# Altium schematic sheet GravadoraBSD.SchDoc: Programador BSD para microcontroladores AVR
size A4; Author: Geovany Araujo Borges
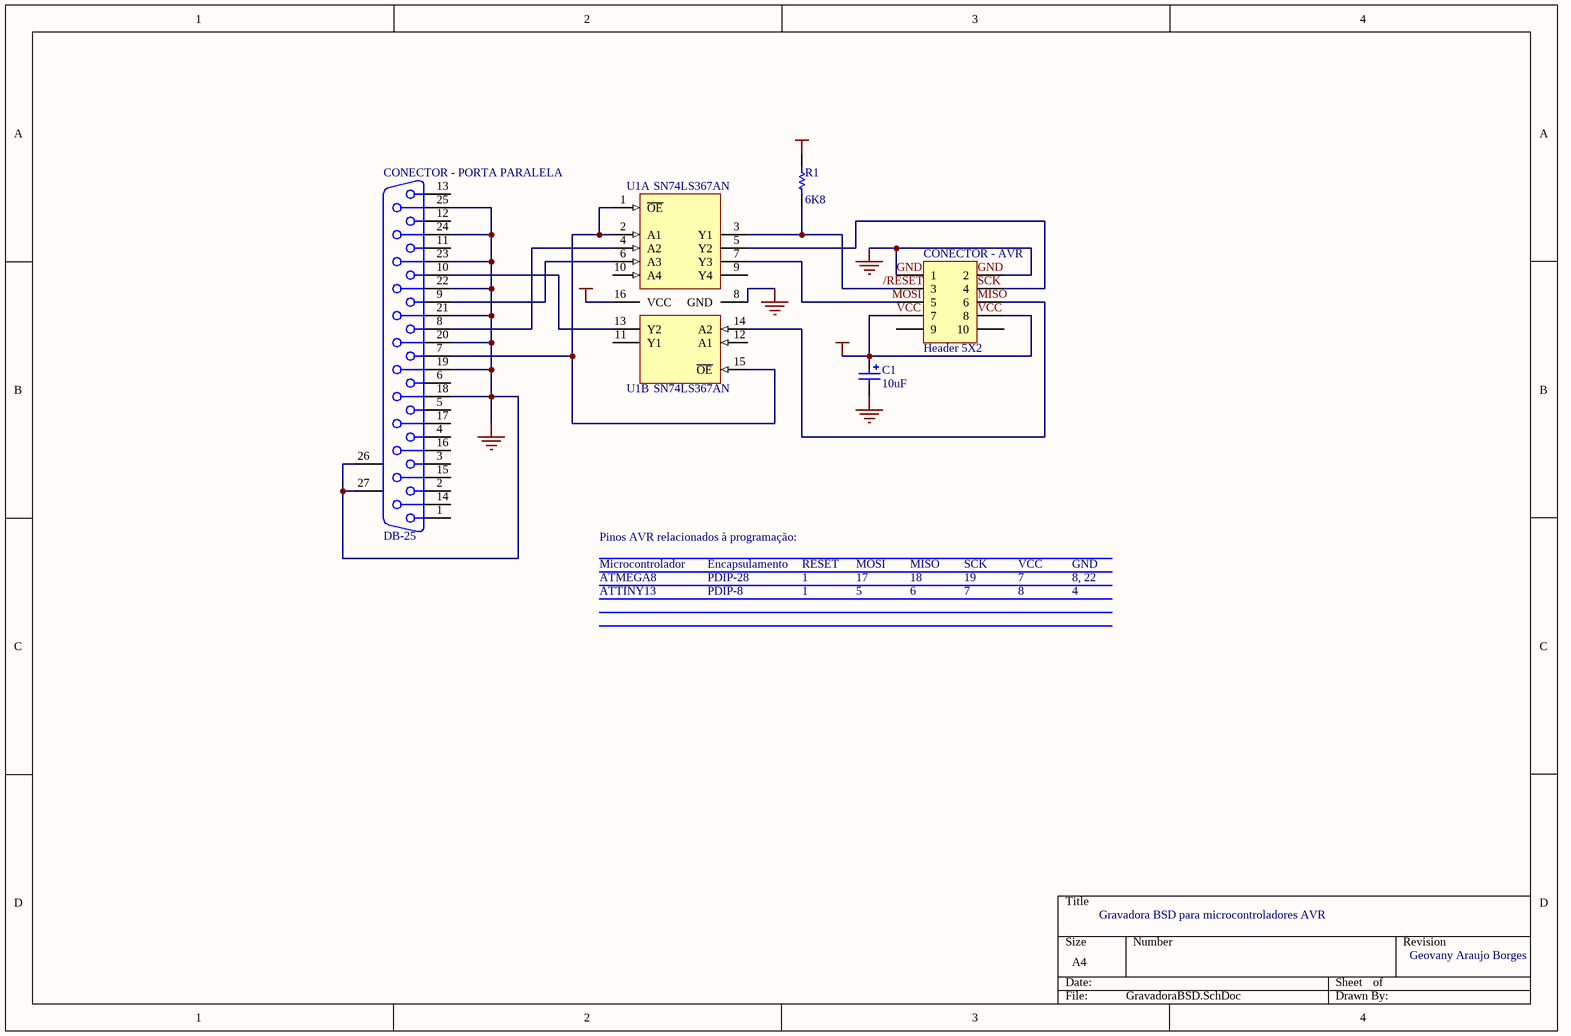
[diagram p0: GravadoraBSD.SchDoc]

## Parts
C1  value 10uF  [RB7.6-15]
CONECTOR_-_AVR  Header 5X2  [HDR2X5]
CONECTOR_-_PORTA_PARALELA  DB-25  [DSUB1.385-2H25A]
R1  value 6K8  [AXIAL-0.3]
U1  SN74LS367AN  [DIP-16/X1.5]  (parts A,B of 2)

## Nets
GND: C1.1 C1.2 CONECTOR_-_AVR.1 CONECTOR_-_AVR.2 CONECTOR_-_AVR.7 CONECTOR_-_AVR.8 CONECTOR_-_PORTA_PARALELA.18 CONECTOR_-_PORTA_PARALELA.19 CONECTOR_-_PORTA_PARALELA.20 CONECTOR_-_PORTA_PARALELA.21 CONECTOR_-_PORTA_PARALELA.22 CONECTOR_-_PORTA_PARALELA.23 CONECTOR_-_PORTA_PARALELA.24 CONECTOR_-_PORTA_PARALELA.25 CONECTOR_-_PORTA_PARALELA.26(MH1) CONECTOR_-_PORTA_PARALELA.27(MH2) R1.2 U1.8(GND) U1.16(VCC)  [also labelled +5V, VCC]
   MOSI: CONECTOR_-_AVR.5 U1.7(Y3)
/RESET: CONECTOR_-_AVR.3 R1.1 U1.3(Y1)
NetCONECTOR_-_AVR_4: CONECTOR_-_AVR.4 U1.5(Y2)
NetCONECTOR_-_AVR_6: CONECTOR_-_AVR.6 U1.14(A2)
NetCONECTOR_-_PORTA_PARALELA_7: CONECTOR_-_PORTA_PARALELA.7 U1.1(~{OE}) U1.2(A1) U1.15(~{OE})
NetCONECTOR_-_PORTA_PARALELA_8: CONECTOR_-_PORTA_PARALELA.8 U1.4(A2)
NetCONECTOR_-_PORTA_PARALELA_9: CONECTOR_-_PORTA_PARALELA.9 U1.6(A3)
NetCONECTOR_-_PORTA_PARALELA_10: CONECTOR_-_PORTA_PARALELA.10 U1.13(Y2)

Not connected (* = marked no-connect by the designer): CONECTOR_-_AVR 9 10; CONECTOR_-_PORTA_PARALELA 1 2 3 4 5 6 11 12 13 14 15 16 17; U1 9(Y4) 10(A4) 11(Y1) 12(A1)

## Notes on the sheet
- Pinos AVR relacionados à programação:
- Microcontrolador
- ATMEGA8
- Encapsulamento
- PDIP-28
- RESET
- 1
- MOSI
- 17
- MISO
- 18
- SCK
- 19
- VCC
- 7
- GND
- 8, 22
- ATTINY13
- PDIP-8
- 5
- 6
- 8
- 4
- Gravadora BSD para microcontroladores AVR
- Geovany Araujo Borges
- Labels drawn without touching a wire or pin: GND, MISO, SCK, VCC

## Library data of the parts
C1 = Cap Pol1: Polarized Capacitor (Radial); Manufacturer: Generic Components; Class I: Passive
CONECTOR_-_AVR = Header 5X2: Header, 5-Pin, Dual row; Manufacturer: Generic Components; Class I: Connector
CONECTOR_-_PORTA_PARALELA = D Connector 25: Receptacle Assembly, 25 Position, Right Angle; Manufacturer: Generic Components; Package Information: Latest Revision: U; Positions: 25
R1 = Res1: Resistor; Manufacturer: Generic Components; Class I: Passive
U1 = SN74LS367AN: Hex Bus Driver with 3-State Outputs; Manufacturer: Texas Instruments; Class I: Logic; Class II: Buffer/Line Driver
